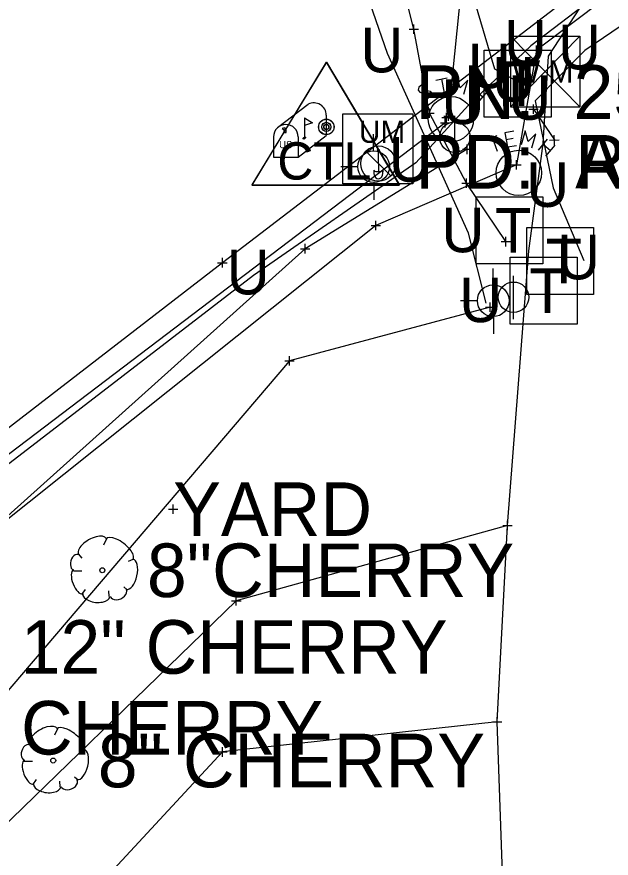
# Model space of a CAD drawing. Extents: x -1 to 1157254, y -1 to 2021979.
# Drawn here: x 1150283 to 1150363, y 2019513.5 to 2019626.6 of the extents above; entities that cross this region are included whole.
import ezdxf

# ---------------------------------------------------------------- set-up
doc = ezdxf.new("R2010")
doc.units = 0
for name, color, linetype in [('S_AREA_CALC', 7, 'Continuous'), ('S_BUILDING_ANNOT', 7, 'Continuous'), ('S_CAL_CORNER', 7, 'Continuous'), ('S_CAL_CORNER_ANNOT', 7, 'Continuous'), ('S_CATCH_BASIN', 7, 'Continuous'), ('S_CATCH_BASIN_ANNOT', 7, 'Continuous'), ('S_CONTOUR_ANNOT', 7, 'Continuous'), ('S_CONTOUR_MAJOR', 7, 'Continuous'), ('S_CROSS_DRAIN', 7, 'Continuous'), ('S_CTL_TABLE', 7, 'Continuous'), ('S_CURB', 7, 'Continuous'), ('S_DITCHLINE', 7, 'Continuous'), ('S_DROP_INLET', 7, 'Continuous'), ('S_DTM_PAVEMENT', 7, 'Continuous'), ('S_EDGE_BITUMINOUS_ANNOT', 7, 'Continuous'), ('S_FENCE', 7, 'Continuous'), ('S_GAS_PUMP_ISLAND_ANNOT', 7, 'Continuous'), ('S_GAS_UTILITIES', 7, 'Continuous'), ('S_GATE', 7, 'Continuous'), ('S_GATE_ANNOT', 7, 'Continuous')]:
    doc.layers.add(name, color=color, linetype=linetype)

msp = doc.modelspace()

# ---------------------------------------------------------------- linework, layer by layer
at = {"layer": 'S_AREA_CALC'}
for p, q in [((1150324.67, 2019620.5), (1150314.64, 2019603.99)), ((1150324.69, 2019620.52), (1150314.66, 2019604.01)), ((1150324.67, 2019620.5), (1150334.49, 2019603.99)), ((1150324.69, 2019620.52), (1150334.51, 2019604.01)), ((1150314.64, 2019603.99), (1150334.49, 2019603.99)), ((1150314.66, 2019604.01), (1150334.51, 2019604.01))]:
    msp.add_line(p, q, dxfattribs=at)
for centre, radius in [((1150324.67, 2019611.8), 1.04), ((1150324.69, 2019611.82), 1.04), ((1150324.67, 2019611.8), 0.609), ((1150324.69, 2019611.82), 0.609), ((1150324.67, 2019611.8), 0.344), ((1150324.69, 2019611.82), 0.344)]:
    msp.add_circle(centre, radius, dxfattribs=at)
at = {"layer": 'S_BUILDING_ANNOT'}
for p, q in [((1150336.47, 2019624.31), (1150336.47, 2019625.58)), ((1150335.83, 2019624.94), (1150337.1, 2019624.95)), ((1150336.47, 2019624.94), (1150336.47, 2019624.94)), ((1150352.34, 2019622.15), (1150353.61, 2019622.15)), ((1150352.98, 2019621.51), (1150352.98, 2019622.78)), ((1150352.98, 2019622.15), (1150352.98, 2019622.15)), ((1150338.58, 2019613.04), (1150338.58, 2019614.31)), ((1150351.91, 2019614.21), (1150353.18, 2019614.21)), ((1150352.55, 2019613.57), (1150352.54, 2019614.84)), ((1150352.54, 2019614.21), (1150352.54, 2019614.21)), ((1150337.94, 2019613.68), (1150339.21, 2019613.68)), ((1150338.58, 2019613.68), (1150338.58, 2019613.68)), ((1150340.2, 2019613.08), (1150341.48, 2019613.08)), ((1150340.5, 2019613.26), (1150341.77, 2019613.26)), ((1150340.68, 2019611.73), (1150340.68, 2019613)), ((1150340.84, 2019612.44), (1150340.84, 2019613.71)), ((1150340.84, 2019613.08), (1150340.84, 2019613.08)), ((1150341.14, 2019612.63), (1150341.14, 2019613.9)), ((1150341.14, 2019613.26), (1150341.14, 2019613.26)), ((1150340.05, 2019612.36), (1150341.32, 2019612.37)), ((1150340.68, 2019612.36), (1150340.68, 2019612.36)), ((1150355.36, 2019609.42), (1150355.35, 2019610.69)), ((1150354.72, 2019610.05), (1150355.99, 2019610.06)), ((1150355.36, 2019610.06), (1150355.36, 2019610.06)), ((1150350.25, 2019606.08), (1150350.25, 2019607.35)), ((1150349.61, 2019606.71), (1150350.89, 2019606.72)), ((1150350.25, 2019606.72), (1150350.25, 2019606.72)), ((1150342.92, 2019604.24), (1150344.19, 2019604.25)), ((1150343.56, 2019603.61), (1150343.55, 2019604.88)), ((1150343.55, 2019604.25), (1150343.55, 2019604.25)), ((1150330.7, 2019598.55), (1150331.98, 2019598.55)), ((1150331.34, 2019597.91), (1150331.34, 2019599.19)), ((1150331.34, 2019598.55), (1150331.34, 2019598.55)), ((1150348.2, 2019596.39), (1150349.47, 2019596.39)), ((1150348.84, 2019595.75), (1150348.84, 2019597.02)), ((1150348.84, 2019596.39), (1150348.84, 2019596.39)), ((1150310.69, 2019592.93), (1150310.69, 2019594.2)), ((1150310.05, 2019593.56), (1150311.33, 2019593.56)), ((1150310.69, 2019593.56), (1150310.69, 2019593.56)), ((1150304.08, 2019559.78), (1150304.08, 2019561.05)), ((1150303.44, 2019560.42), (1150304.72, 2019560.42)), ((1150304.08, 2019560.42), (1150304.08, 2019560.42))]:
    msp.add_line(p, q, dxfattribs=at)
at = {"layer": 'S_CAL_CORNER'}
for p, q in [((1150330.01, 2019608.56), (1150333.35, 2019605.22)), ((1150331.52, 2019608.78), (1150331.83, 2019608.78)), ((1150331.68, 2019606.89), (1150331.68, 2019608.63)), ((1150331.68, 2019606.89), (1150331.68, 2019605.83)), ((1150331.08, 2019605.99), (1150331.08, 2019605.8)), ((1150332.27, 2019605.99), (1150332.28, 2019605.77))]:
    msp.add_line(p, q, dxfattribs=at)
msp.add_lwpolyline([(1150326.91, 2019613.55), (1150336.33, 2019613.55), (1150336.33, 2019604.14), (1150326.91, 2019604.14)], close=True, dxfattribs=at)
msp.add_circle((1150331.68, 2019606.89), 2.36, dxfattribs=at)
for centre, radius, start, end in [((1150331.68, 2019608.78), 0.156, 180, 0), ((1150331.5, 2019606.38), 0.58, 223.1344, 287.472), ((1150331.85, 2019606.39), 0.58, 252.528, 316.8656)]:
    msp.add_arc(centre, radius, start, end, dxfattribs=at)
msp.add_ellipse((1150331.68, 2019605.65), major_axis=(0, -0.82), ratio=0.744362, start_param=4.519801, end_param=8.000179, dxfattribs=at)
at = {"layer": 'S_CAL_CORNER_ANNOT'}
msp.add_lwpolyline([(1150682.05, 2019865.85), (1150601.54, 2019813.47), (1150510.58, 2019743.97), (1150405.28, 2019665.92), (1150310.69, 2019593.56), (1150188.92, 2019499.64), (1150039.45, 2019388.15), (1149962.15, 2019331.17), (1149944.63, 2019319.08), (1149774.15, 2019191.52), (1149712.73, 2019145.6), (1149665.81, 2019108.74), (1149605.46, 2019057.66), (1149527.46, 2018983.58), (1149450.12, 2018902.93), (1149278.32, 2018738.82), (1149257.2, 2018716.38), (1149237.23, 2018691.25), (1149165.09, 2018617.77), (1149125.26, 2018579.57), (1149069.5, 2018523.84), (1149012.03, 2018473.77), (1148938.88, 2018408.55)], dxfattribs=at)
at = {"layer": 'S_CATCH_BASIN'}
for p, q in [((1150341.96, 2019607.51), (1150341.96, 2019613.3)), ((1150331.04, 2019608.58), (1150331.04, 2019610.82)), ((1150328.95, 2019606.45), (1150326.63, 2019606.45)), ((1150331.12, 2019602.03), (1150331.12, 2019604.35)), ((1150347.13, 2019590.54), (1150347.13, 2019592.79)), ((1150349.87, 2019585.98), (1150349.87, 2019591.77)), ((1150345.04, 2019588.41), (1150342.72, 2019588.41)), ((1150347.21, 2019584), (1150347.21, 2019586.32))]:
    msp.add_line(p, q, dxfattribs=at)
for centre, radius in [((1150341.96, 2019610.44), 2.05), ((1150331.05, 2019606.47), 2.13), ((1150347.13, 2019588.44), 2.13), ((1150349.87, 2019588.91), 2.05)]:
    msp.add_circle(centre, radius, dxfattribs=at)
at = {"layer": 'S_CATCH_BASIN_ANNOT'}
for p, q in [((1150346.25, 2019610.12), (1150347.68, 2019610.66)), ((1150349.93, 2019611.25), (1150348.69, 2019611.01)), ((1150348.69, 2019611.01), (1150349.04, 2019609.12)), ((1150346.99, 2019610.43), (1150347.68, 2019608.57)), ((1150349.81, 2019610.24), (1150348.88, 2019610.08)), ((1150353.22, 2019608.69), (1150354.46, 2019610.16)), ((1150349.04, 2019609.12), (1150350.28, 2019609.31)), ((1150353.88, 2019609.46), (1150354.85, 2019608.65)), ((1150355.43, 2019609.35), (1150354.19, 2019607.88))]:
    msp.add_line(p, q, dxfattribs=at)
for points in [[(1150345.94, 2019613.13), (1150345.94, 2019622.12), (1150354.93, 2019622.12), (1150354.93, 2019613.13)], [(1150344.82, 2019593.4), (1150344.82, 2019602.39), (1150353.82, 2019602.39), (1150353.82, 2019593.4)], [(1150351.64, 2019589.28), (1150351.64, 2019598.28), (1150360.63, 2019598.28), (1150360.63, 2019589.28)], [(1150349.43, 2019585.3), (1150349.43, 2019594.29), (1150358.43, 2019594.29), (1150358.43, 2019585.3)]]:
    msp.add_lwpolyline(points, close=True, dxfattribs=at)
msp.add_lwpolyline([(1150352.33, 2019609), (1150352.87, 2019610.86), (1150351.83, 2019609.85), (1150351.44, 2019611.28), (1150350.9, 2019609.42)], dxfattribs=at)
msp.add_circle((1150350.58, 2019605.63), 3.05, dxfattribs=at)
at = {"layer": 'S_CONTOUR_ANNOT'}
for p, q in [((1150349.46, 2019624), (1150358.8, 2019624)), ((1150349.46, 2019624), (1150349.46, 2019614.51)), ((1150349.46, 2019624), (1150358.8, 2019614.51)), ((1150358.8, 2019624), (1150349.46, 2019614.51)), ((1150358.8, 2019624), (1150358.8, 2019614.51)), ((1150349.46, 2019614.51), (1150358.8, 2019614.51))]:
    msp.add_line(p, q, dxfattribs=at)
at = {"layer": 'S_CROSS_DRAIN'}
for p, q in [((1150318.12, 2019611.75), (1150322.25, 2019614.85)), ((1150321.73, 2019613.03), (1150321.73, 2019610.32)), ((1150324.68, 2019613.38), (1150324.68, 2019610.67)), ((1150320.89, 2019607.76), (1150324.68, 2019610.67)), ((1150317.56, 2019610.47), (1150317.56, 2019607.76)), ((1150320.89, 2019610.47), (1150320.89, 2019607.76)), ((1150317.56, 2019607.76), (1150320.89, 2019607.76))]:
    msp.add_line(p, q, dxfattribs=at)
for points in [[(1150321.73, 2019613.03), (1150322.84, 2019612.37), (1150321.73, 2019612.02)], [(1150318.75, 2019611.59), (1150318.97, 2019611.45), (1150318.97, 2019611.06), (1150319.27, 2019611.06), (1150319.27, 2019611.42), (1150319.08, 2019611.67), (1150318.75, 2019611.61)]]:
    msp.add_lwpolyline(points, dxfattribs=at)
for centre, end in [((1150323.02, 2019613.38), 117.5718), ((1150319.23, 2019610.47), 180)]:
    msp.add_arc(centre, 1.66, 0, end, dxfattribs=at)
msp.add_ellipse((1150321.73, 2019610.32), major_axis=(0.145, 0.132), ratio=0.564646, dxfattribs=at)
at = {"layer": 'S_CTL_TABLE'}
for p, q in [((1150343.01, 2019608.8), (1150344.29, 2019608.8)), ((1150343.65, 2019608.17), (1150343.65, 2019609.44)), ((1150343.65, 2019608.8), (1150343.65, 2019608.8)), ((1150321.84, 2019594.81), (1150321.84, 2019596.08)), ((1150321.21, 2019595.44), (1150322.48, 2019595.44)), ((1150321.84, 2019595.44), (1150321.84, 2019595.44)), ((1150346.73, 2019586.94), (1150346.72, 2019588.22)), ((1150346.09, 2019587.58), (1150347.36, 2019587.58)), ((1150346.72, 2019587.58), (1150346.72, 2019587.58)), ((1150319.09, 2019580.36), (1150320.36, 2019580.37)), ((1150319.73, 2019579.73), (1150319.73, 2019581)), ((1150319.73, 2019580.37), (1150319.73, 2019580.37)), ((1150349.05, 2019557.6), (1150349.05, 2019558.87)), ((1150348.42, 2019558.23), (1150349.69, 2019558.23)), ((1150349.05, 2019558.23), (1150349.05, 2019558.23)), ((1150312.57, 2019547.48), (1150312.56, 2019548.75)), ((1150311.93, 2019548.11), (1150313.2, 2019548.11)), ((1150312.56, 2019548.11), (1150312.56, 2019548.11)), ((1150347.03, 2019531.84), (1150348.3, 2019531.84)), ((1150347.67, 2019531.2), (1150347.67, 2019532.47)), ((1150347.67, 2019531.84), (1150347.67, 2019531.84)), ((1150310.7, 2019527.13), (1150310.7, 2019528.41)), ((1150310.06, 2019527.77), (1150311.34, 2019527.77)), ((1150310.7, 2019527.77), (1150310.7, 2019527.77))]:
    msp.add_line(p, q, dxfattribs=at)
at = {"layer": 'S_CURB'}
for p, q in [((1150295.1, 2019556.45), (1150294.71, 2019555.59)), ((1150291.3, 2019554.43), (1150291.8, 2019553.85)), ((1150298.66, 2019553.66), (1150298, 2019553.39)), ((1150290.64, 2019552.11), (1150291.77, 2019552.11)), ((1150291.8, 2019548.93), (1150292.27, 2019549.63)), ((1150297.89, 2019549.55), (1150297.42, 2019549.98)), ((1150295.48, 2019548.66), (1150295.41, 2019549.44)), ((1150288.49, 2019530.87), (1150288.1, 2019530.02)), ((1150284.69, 2019528.85), (1150285.2, 2019528.27)), ((1150292.05, 2019528.08), (1150291.4, 2019527.81)), ((1150284.04, 2019526.53), (1150285.16, 2019526.53)), ((1150285.2, 2019523.35), (1150285.66, 2019524.05)), ((1150288.88, 2019523.08), (1150288.8, 2019523.86)), ((1150291.28, 2019523.97), (1150290.81, 2019524.4))]:
    msp.add_line(p, q, dxfattribs=at)
for centre in [(1150294.54, 2019552.2), (1150287.93, 2019526.62)]:
    msp.add_circle(centre, 0.34, dxfattribs=at)
for centre, major_axis, ratio, start_param, end_param in [((1150293.2, 2019555.4), (1.86, 1.08), 0.471018, 0, 3.141593), ((1150296.86, 2019555.08), (-1.81, 1.36), 0.405113, 3.141593, 6.283186), ((1150290.97, 2019553.29), (0.31, 1.03), 0.646762, 0, 3.141593), ((1150298.21, 2019551.67), (0.46, 2.04), 0.482994, 3.141593, 6.283185), ((1150291.27, 2019550.64), (-0.61, 1.6), 0.420543, 6.283185, 9.424777), ((1150296.69, 2019549.15), (1.09, 0.46), 0.711534, 3.141592, 6.283185), ((1150293.73, 2019548.86), (-1.83, 0.19), 0.529943, 0, 3.141593), ((1150286.6, 2019529.83), (1.86, 1.08), 0.471018, 0, 3.141593), ((1150290.25, 2019529.5), (-1.81, 1.36), 0.405113, 3.141593, 6.283186), ((1150284.36, 2019527.71), (0.31, 1.03), 0.646762, 0, 3.141593), ((1150291.6, 2019526.1), (0.46, 2.04), 0.482994, 3.141593, 6.283185), ((1150284.67, 2019525.06), (-0.61, 1.6), 0.420543, 6.283185, 9.424777), ((1150290.08, 2019523.58), (1.09, 0.46), 0.711534, 3.141592, 6.283185), ((1150287.13, 2019523.28), (-1.83, 0.19), 0.529943, 0, 3.141593)]:
    msp.add_ellipse(centre, major_axis=major_axis, ratio=ratio, start_param=start_param, end_param=end_param, dxfattribs=at)
at = {"layer": 'S_DITCHLINE'}
for p, q in [((1150337.66, 2019617.54), (1150337.12, 2019617.15)), ((1150338.09, 2019617.46), (1150337.66, 2019617.54)), ((1150339.41, 2019618.12), (1150340.92, 2019618.39)), ((1150340.18, 2019618.27), (1150340.53, 2019616.33)), ((1150337.12, 2019617.15), (1150337.04, 2019616.76)), ((1150337.04, 2019616.76), (1150337.24, 2019616.49)), ((1150337.24, 2019616.49), (1150337.66, 2019616.37)), ((1150337.66, 2019616.37), (1150338.21, 2019616.72)), ((1150338.21, 2019616.72), (1150338.67, 2019616.64)), ((1150338.67, 2019616.64), (1150338.82, 2019616.37)), ((1150338.82, 2019616.37), (1150338.75, 2019615.95)), ((1150344.09, 2019615.91), (1150345.33, 2019617.38)), ((1150344.75, 2019616.68), (1150345.72, 2019615.87)), ((1150346.3, 2019616.57), (1150345.06, 2019615.09)), ((1150338.21, 2019615.56), (1150337.82, 2019615.64)), ((1150338.75, 2019615.95), (1150338.21, 2019615.56))]:
    msp.add_line(p, q, dxfattribs=at)
for points in [[(1150341.14, 2019613.26), (1150352.37, 2019724.05)], [(1150343.2, 2019616.22), (1150343.74, 2019618.08), (1150342.7, 2019617.07), (1150342.31, 2019618.5), (1150341.77, 2019616.64)], [(1150340.68, 2019612.36), (1149611.97, 2019059.3)]]:
    msp.add_lwpolyline(points, dxfattribs=at)
msp.add_circle((1150341.45, 2019612.85), 3.05, dxfattribs=at)
at = {"layer": 'S_DROP_INLET'}
for points in [[(1150852.18, 2019973.05), (1150778.54, 2019928.45), (1150770.16, 2019919.18), (1150703.8, 2019877.29), (1150608.63, 2019809.12), (1150513.43, 2019739.89), (1150405.92, 2019663.65), (1150352.2, 2019622.72), (1150343.81, 2019614.74), (1150336.72, 2019606.98), (1150314.89, 2019591.84), (1150193.25, 2019498.28), (1150112.69, 2019435.49), (1150059.59, 2019406.16), (1150037.88, 2019389.79), (1149962.99, 2019329.91), (1149914.05, 2019297.4), (1149863.26, 2019256.98)], [(1150853.56, 2019969.99), (1150781.71, 2019924.44), (1150774.41, 2019914.43), (1150697.13, 2019863.12), (1150609.24, 2019805.57), (1150516.58, 2019735.98), (1150408.74, 2019655.56), (1150359.48, 2019622.09), (1150352.77, 2019615.32), (1150355.2, 2019603.6), (1150359.35, 2019593.87)], [(1150350.62, 2019617.77), (1150347.34, 2019619.56), (1150333.35, 2019666.91)], [(1150346.18, 2019588.1), (1150343.79, 2019597.51), (1150332.89, 2019621.7), (1150320.56, 2019657.25)]]:
    msp.add_lwpolyline(points, dxfattribs=at)
at = {"layer": 'S_DTM_PAVEMENT'}
msp.add_lwpolyline([(1150352.54, 2019614.21), (1150355.36, 2019610.06)], dxfattribs=at)
at = {"layer": 'S_EDGE_BITUMINOUS_ANNOT'}
for points in [[(1150343.65, 2019608.8), (1150321.84, 2019595.44), (1150270.77, 2019549.67), (1150236.43, 2019533.28), (1150224.63, 2019524.31)], [(1150346.72, 2019587.58), (1150319.73, 2019580.37), (1150276.31, 2019529.58), (1150250.87, 2019524.53), (1150230.87, 2019512.6)], [(1150349.05, 2019558.23), (1150312.56, 2019548.11), (1150274.78, 2019511.51), (1150257.47, 2019504.01), (1150235.9, 2019492.57)], [(1150347.67, 2019531.84), (1150310.7, 2019527.77), (1150271.25, 2019485.26), (1150247.21, 2019480.94), (1150231.53, 2019471.46), (1150209.53, 2019459.1)]]:
    msp.add_lwpolyline(points, dxfattribs=at)
at = {"layer": 'S_FENCE'}
for points in [[(1150775.16, 2019913.88), (1150697.15, 2019862.05), (1150611.54, 2019805.47), (1150516.86, 2019735.37), (1150402.98, 2019659.79), (1150352.98, 2019622.15), (1150350.25, 2019606.72), (1150331.34, 2019598.55), (1150196.24, 2019490.87), (1150043.62, 2019380.11), (1149966.77, 2019324.72), (1149934.21, 2019308.48), (1149916.33, 2019289.12), (1149866.68, 2019250.91)], [(1150348.84, 2019596.39), (1150343.55, 2019604.25), (1150338.58, 2019613.68), (1150336.47, 2019624.94), (1150327.49, 2019660.32)]]:
    msp.add_lwpolyline(points, dxfattribs=at)
at = {"layer": 'S_GAS_PUMP_ISLAND_ANNOT'}
msp.add_lwpolyline([(1150348.96, 2019494.95), (1150347.67, 2019531.84), (1150349.05, 2019558.23), (1150351.95, 2019595.15), (1150353.86, 2019609.6), (1150354.57, 2019621.34), (1150379.48, 2019659.47), (1150390.47, 2019667.69), (1150402.5, 2019676.7), (1150413.44, 2019685.01), (1150425.39, 2019694.35), (1150438.68, 2019703.56)], dxfattribs=at)

# ---------------------------------------------------------------- texts
at = {"layer": 'S_AREA_CALC'}
for p in [(1150318.09, 2019604.73), (1150318.11, 2019604.75)]:
    msp.add_text('CTL', height=4.998, dxfattribs=at).set_placement(p)
at = {"layer": 'S_CAL_CORNER'}
msp.add_text('UM', height=2.999, dxfattribs=at).set_placement((1150329.06, 2019609.67))
at = {"layer": 'S_CATCH_BASIN_ANNOT'}
for p in [(1150348.5, 2019614.63), (1150347.39, 2019594.9), (1150354.2, 2019590.78), (1150351.99, 2019586.8)]:
    msp.add_text('T', height=6, dxfattribs=at).set_placement(p)
at = {"layer": 'S_CONTOUR_ANNOT'}
msp.add_text('W M', height=2.999, dxfattribs=at).set_placement((1150349.67, 2019617.77))
at = {"layer": 'S_CONTOUR_MAJOR'}
for p in [(1150348.58, 2019620.17), (1150355.85, 2019619.55), (1150329.26, 2019619.15), (1150343.71, 2019617.01), (1150346.99, 2019615.22), (1150349.14, 2019612.77), (1150340.18, 2019612.19), (1150333.09, 2019604.44), (1150351.57, 2019601.06), (1150340.16, 2019594.96), (1150355.72, 2019591.32), (1150311.27, 2019589.3), (1150342.55, 2019585.56)]:
    msp.add_text('U', height=6, dxfattribs=at).set_placement(p)
at = {"layer": 'S_CROSS_DRAIN'}
msp.add_text('US', height=0.96, dxfattribs=at).set_placement((1150318.33, 2019608.95))
at = {"layer": 'S_GAS_UTILITIES'}
for s, p in [('PN: ', (1150336.67, 2019612.88)), ('PN: ', (1150336.69, 2019612.9)), ('251', (1150357.94, 2019612.88)), ('25', (1150357.96, 2019612.9)), ('PD: ', (1150336.67, 2019603.52)), ('PD: ', (1150336.69, 2019603.54)), ('AHTD STD. MON. STAMPED PN:25', (1150358.16, 2019603.54)), ('RBR ALUM CAP', (1150358.15, 2019603.52))]:
    msp.add_text(s, height=7.2, dxfattribs=at).set_placement(p)
at = {"layer": 'S_GATE'}
msp.add_text('YARD', height=7.2, dxfattribs=at).set_placement((1150304.08, 2019556.82))
at = {"layer": 'S_GATE_ANNOT'}
for s, p in [('8"CHERRY', (1150300.54, 2019548.6)), ('12" CHERRY', (1150283.55, 2019538.29)), ('12" CHERRY', (1150266.8, 2019527.43)), ('8" CHERRY', (1150293.93, 2019523.02))]:
    msp.add_text(s, height=7.2, dxfattribs=at).set_placement(p)

doc.saveas('drawing.dxf')
